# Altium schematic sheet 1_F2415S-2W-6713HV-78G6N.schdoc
size 289 x 200 mm; Name: default297x210; Symbol: default297x210; Device: default297x210; Date: 2025.06.19; Rev: V1.1; Size: "A4"; Id: /; File: F2415S-2W-6713HV-78G6N; Sheet: /; @Page No: 1; @Page Count: 1; @Schematic Name: F2415S-2W-6713HV-78G6N; @Project Name: F2415S-2W-6713HV-78G6N; @Board Name: F2415S-2W-6713HV-78G6N; @Update Date: 2025-06-19; @Create Time: 17:16:44; @Update Time: 17:16:50; @Page Name: F2415S-2W-6713HV-78G6N; @Create Date: 2025-06-19
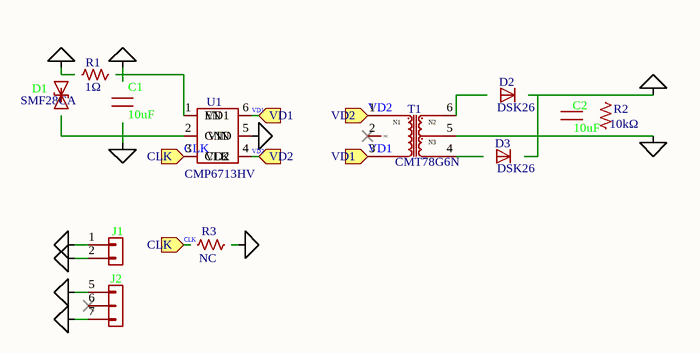
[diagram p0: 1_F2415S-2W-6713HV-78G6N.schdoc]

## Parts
C1  10uF  [C0603]
C2  10uF  [C0603]
D1  SMF28CA  [SOD-123FL_L2.8-W1.8-LS3.7-BI]
D2  DSK26  [SOD-123_L2.8-W1.8-LS3.7-RD]
D3  DSK26  [SOD-123_L2.8-W1.8-LS3.7-RD]
J1  Connector_Generic_Conn_01x04  [coileasy:PinHeader_01x02_P2.54mm_Vertical]  (value not drawn)
J2  Connector_Generic_Conn_01x04  [coileasy:PinHeader_01x03_1_P2.54mm_Vertical]  (value not drawn)
R1  1Ω  [R0603]
R2  10kΩ  [R0603]
R3  NC  [R0603]
T1  CMT78G6N  [XFMR-SMD_6P-L9.3-W8.8-P2.54-LS12.6]
U1  value CMP6713HV  [coileasy:SOT-23-6]  (hidden comment: Coileasy_SOT23-6)

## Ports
CLK (in), VD1 (in), VD2 (in)

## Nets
0V: J2.5 T1.5
+VO: J2.7
GND: J1.2 U1.2(GND)
VCC: U1.1(EN) U1.5(VIN)
VIN: J1.1
CLK: U1.3(CLK) ; port CLK
VD1: T1.3 U1.6(VD1) ; port VD1
VD2: T1.1 U1.4(VD2) ; port VD2

Not connected (* = marked no-connect by the designer): J2 6*; T1 2* 4 6

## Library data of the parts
C1 = CGA0603X5R106M350JT: Manufacturer: HRE(芯声); Symbol: My_Library_C; Add into BOM: yes; Tolerance: ±20%; Voltage Rating: 35V; Temperature Coefficient: X5R
C2 = 0603X106M250NT: Manufacturer: FH(风华); Symbol: My_Library_C; Add into BOM: yes; Tolerance: ±20%; Voltage Rating: 25V; Temperature Coefficient: X5R
D1 = SMF28CA_C364280: Manufacturer: MDD(辰达半导体); Symbol: Device_D_TVS; Add into BOM: yes; polarity: 双向; Reverse Stand-Off Voltage (Vrwm): 28V; Maximum Clamping Voltage: 45.4V; Peak Pulse Current (Ipp): 4.4A; Peak Pulse Power Dissipation (Ppp): 200W; Breakdown Voltage: 34.4V; Reverse Leakage Current (Ir): 1uA; Type: TVS
D2 D3 = DSK26_C50553: Manufacturer: MDD(辰达半导体); Symbol: My_Library_D; Add into BOM: yes; Diode Configuration: 独立式; Forward Voltage (Vf@If): 700mV@2A; Reverse Voltage (Vr): 60V; Rectified Current: 2A; Reverse Leakage Current (Ir): 500uA@60V
J1 = Connector_Generic_Conn_01x04: Symbol: Conn_01x04_1; ki_fp_filters: Connector*:*_1x??_*; Value: Conn_01x02; Add into BOM: yes
J2 = Connector_Generic_Conn_01x04: ki_fp_filters: Connector*:*_1x??_*; Value: Conn_01x03; Add into BOM: yes
R1 = RC0603FR-071RL: Manufacturer: YAGEO(国巨); Symbol: My_Library_R; Add into BOM: yes; Tolerance: ±1%; Power(Watts): 100mW; Overload Voltage (Max): 75V; Temperature Coefficient: ±200ppm/℃
R2 = RC0603FR-0710KL: Manufacturer: YAGEO(国巨); Symbol: My_Library_R; Add into BOM: yes; Tolerance: ±1%; Power(Watts): 100mW; Overload Voltage (Max): 75V; Temperature Coefficient: ±100ppm/℃
R3 = RC0603FR-0715KL: Symbol: My_Library_R; Add into BOM: yes; Tolerance: ±1%; Power(Watts): 100mW; Overload Voltage (Max): 75V; Temperature Coefficient: ±100ppm/℃
T1 = CMT78G6N: Manufacturer: coileasy(线易); Symbol: MYLibrary _CMT6870N; Add into BOM: yes
U1 = Coileasy_SOT23-6: Add into BOM: yes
